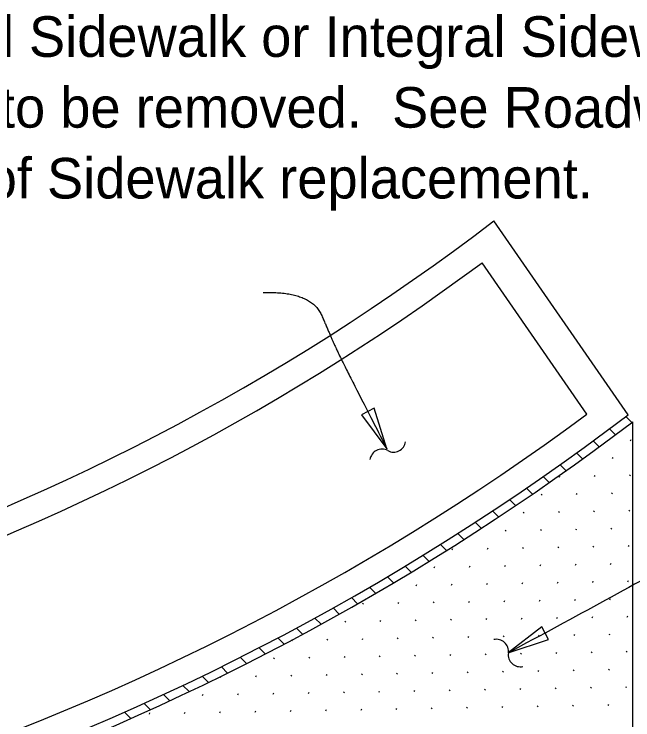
# Model space of a CAD drawing. Extents: x 21526.6 to 21595.9, y 56114.9 to 56157.2.
# Drawn here: x 21559.338 to 21562.412, y 56149.572 to 56153.08 of the extents above; entities that cross this region are included whole.
import ezdxf

# ---------------------------------------------------------------- set-up
doc = ezdxf.new("R2010")
doc.units = 0
for name, color, linetype in [('AdhocPoint_dp', 7, 'Continuous'), ('Patterning', 7, 'Continuous'), ('PlotBorder_dp', 7, 'Continuous')]:
    doc.layers.add(name, color=color, linetype=linetype)

msp = doc.modelspace()

# ---------------------------------------------------------------- linework, layer by layer
at = {"layer": 'AdhocPoint_dp'}
for p, q in [((21562.3881, 56151.0884), (21561.7207, 56152.0524)), ((21562.1837, 56151.0913), (21561.6624, 56151.8443)), ((21562.4118, 56147.2732), (21562.4118, 56151.0541))]:
    msp.add_line(p, q, dxfattribs=at)
for radius, start, end in [(11.3394, 267.40102, 307.51098), (11.4702, 267.84731, 306.6471), (12.5106, 267.64448, 307.24718), (12.3856, 268.00648, 306.50279), (12.5523, 272.40859, 307.2387)]:
    msp.add_arc((21554.816, 56161.0472), radius, start, end, dxfattribs=at)
at = {"layer": 'Patterning'}
for p, q in [((21562.3762, 56151.0794), (21562.4058, 56151.0498)), ((21562.2955, 56151.0186), (21562.3249, 56150.9892)), ((21562.2142, 56150.9585), (21562.244, 56150.9287)), ((21562.4004, 56150.9596), (21562.4036, 56150.9652)), ((21562.1323, 56150.899), (21562.1618, 56150.8695)), ((21562.3111, 56150.8703), (21562.3143, 56150.8759)), ((21562.0498, 56150.84), (21562.0796, 56150.8103)), ((21561.9668, 56150.7817), (21561.9964, 56150.7521)), ((21562.0465, 56150.7778), (21562.0497, 56150.7834)), ((21562.2218, 56150.781), (21562.2251, 56150.7866)), ((21562.3971, 56150.7843), (21562.4004, 56150.7899)), ((21561.8831, 56150.7239), (21561.9128, 56150.6942)), ((21561.9572, 56150.6885), (21561.9605, 56150.6941)), ((21562.1325, 56150.6918), (21562.1358, 56150.6974)), ((21562.3078, 56150.695), (21562.3111, 56150.7006)), ((21561.7989, 56150.6667), (21561.8286, 56150.637)), ((21561.714, 56150.6102), (21561.7438, 56150.5804)), ((21561.868, 56150.5993), (21561.8712, 56150.6048)), ((21562.0433, 56150.6025), (21562.0465, 56150.6081)), ((21562.2186, 56150.6057), (21562.2218, 56150.6113)), ((21562.3939, 56150.609), (21562.3971, 56150.6146)), ((21561.6286, 56150.5542), (21561.6586, 56150.5242)), ((21561.7787, 56150.51), (21561.7819, 56150.5156)), ((21561.954, 56150.5132), (21561.9572, 56150.5188)), ((21562.1293, 56150.5165), (21562.1325, 56150.5221)), ((21562.3046, 56150.5197), (21562.3078, 56150.5253)), ((21561.5425, 56150.4988), (21561.5723, 56150.469)), ((21561.4559, 56150.4441), (21561.4861, 56150.4138)), ((21561.5141, 56150.4175), (21561.5174, 56150.4231)), ((21561.6894, 56150.4207), (21561.6927, 56150.4263)), ((21561.8647, 56150.4239), (21561.868, 56150.4295)), ((21562.04, 56150.4272), (21562.0433, 56150.4328)), ((21562.2153, 56150.4304), (21562.2186, 56150.436)), ((21562.3906, 56150.4337), (21562.3939, 56150.4393)), ((21561.3686, 56150.3899), (21561.3985, 56150.36)), ((21561.6001, 56150.3314), (21561.6034, 56150.337)), ((21561.7755, 56150.3347), (21561.7787, 56150.3403)), ((21561.9508, 56150.3379), (21561.954, 56150.3435)), ((21562.1261, 56150.3412), (21562.1293, 56150.3468)), ((21562.3014, 56150.3444), (21562.3046, 56150.35)), ((21561.2807, 56150.3364), (21561.3109, 56150.3062)), ((21561.4248, 56150.3282), (21561.4281, 56150.3338)), ((21561.1922, 56150.2834), (21561.2223, 56150.2534)), ((21561.3356, 56150.2389), (21561.3388, 56150.2445)), ((21561.5109, 56150.2422), (21561.5141, 56150.2478)), ((21561.6862, 56150.2454), (21561.6894, 56150.251)), ((21561.8615, 56150.2486), (21561.8647, 56150.2542)), ((21562.0368, 56150.2519), (21562.04, 56150.2575)), ((21562.2121, 56150.2551), (21562.2153, 56150.2607)), ((21562.3874, 56150.2584), (21562.3906, 56150.264)), ((21561.1031, 56150.2311), (21561.1333, 56150.2009)), ((21561.0134, 56150.1795), (21561.0436, 56150.1492)), ((21561.5969, 56150.1561), (21561.6001, 56150.1617)), ((21561.7722, 56150.1594), (21561.7755, 56150.165)), ((21561.9475, 56150.1626), (21561.9508, 56150.1682)), ((21562.1228, 56150.1659), (21562.1261, 56150.1715)), ((21562.2981, 56150.1691), (21562.3014, 56150.1747)), ((21560.923, 56150.1284), (21560.9533, 56150.0981)), ((21561.071, 56150.1464), (21561.0742, 56150.152)), ((21561.2463, 56150.1496), (21561.2495, 56150.1552)), ((21561.4216, 56150.1529), (21561.4248, 56150.1585)), ((21560.832, 56150.078), (21560.8624, 56150.0475)), ((21560.9817, 56150.0571), (21560.985, 56150.0627)), ((21561.157, 56150.0604), (21561.1603, 56150.066)), ((21561.3323, 56150.0636), (21561.3356, 56150.0692)), ((21561.5076, 56150.0669), (21561.5109, 56150.0725)), ((21561.6829, 56150.0701), (21561.6862, 56150.0757)), ((21561.8582, 56150.0733), (21561.8615, 56150.0789)), ((21562.0335, 56150.0766), (21562.0368, 56150.0822)), ((21562.2088, 56150.0798), (21562.2121, 56150.0854)), ((21562.3842, 56150.0831), (21562.3874, 56150.0887)), ((21560.7403, 56150.0282), (21560.7707, 56149.9978)), ((21561.5937, 56149.9808), (21561.5969, 56149.9864)), ((21561.769, 56149.9841), (21561.7722, 56149.9897)), ((21561.9443, 56149.9873), (21561.9475, 56149.9929)), ((21562.1196, 56149.9905), (21562.1228, 56149.9961)), ((21562.2949, 56149.9938), (21562.2981, 56149.9994)), ((21560.648, 56149.9791), (21560.6787, 56149.9484)), ((21560.7171, 56149.9646), (21560.7204, 56149.9702)), ((21560.8925, 56149.9679), (21560.8957, 56149.9735)), ((21561.0678, 56149.9711), (21561.071, 56149.9767)), ((21561.2431, 56149.9743), (21561.2463, 56149.9799)), ((21561.4184, 56149.9776), (21561.4216, 56149.9832)), ((21560.5551, 56149.9306), (21560.5856, 56149.9001)), ((21560.4615, 56149.8828), (21560.4925, 56149.8518)), ((21560.6279, 56149.8753), (21560.6311, 56149.8809)), ((21560.8032, 56149.8786), (21560.8064, 56149.8842)), ((21560.9785, 56149.8818), (21560.9817, 56149.8874)), ((21561.1538, 56149.8851), (21561.157, 56149.8907)), ((21561.3291, 56149.8883), (21561.3323, 56149.8939)), ((21561.5044, 56149.8916), (21561.5076, 56149.8972)), ((21561.6797, 56149.8948), (21561.6829, 56149.9004)), ((21561.855, 56149.898), (21561.8582, 56149.9036)), ((21562.0303, 56149.9013), (21562.0335, 56149.9069)), ((21562.2056, 56149.9045), (21562.2088, 56149.9101)), ((21562.3809, 56149.9078), (21562.3842, 56149.9134)), ((21560.3672, 56149.8357), (21560.3979, 56149.8049)), ((21561.5904, 56149.8055), (21561.5937, 56149.8111)), ((21561.7657, 56149.8088), (21561.769, 56149.8144)), ((21561.941, 56149.812), (21561.9443, 56149.8176)), ((21562.1163, 56149.8152), (21562.1196, 56149.8208)), ((21562.2916, 56149.8185), (21562.2949, 56149.8241)), ((21560.2723, 56149.7892), (21560.3034, 56149.7581)), ((21560.3633, 56149.7828), (21560.3665, 56149.7884)), ((21560.5386, 56149.7861), (21560.5418, 56149.7917)), ((21560.7139, 56149.7893), (21560.7171, 56149.7949)), ((21560.8892, 56149.7926), (21560.8925, 56149.7982)), ((21561.0645, 56149.7958), (21561.0678, 56149.8014)), ((21561.2398, 56149.799), (21561.2431, 56149.8046)), ((21561.4151, 56149.8023), (21561.4184, 56149.8079)), ((21560.1767, 56149.7433), (21560.2076, 56149.7124)), ((21560.6246, 56149.7), (21560.6279, 56149.7056)), ((21560.7999, 56149.7033), (21560.8032, 56149.7089)), ((21560.9752, 56149.7065), (21560.9785, 56149.7121)), ((21561.1505, 56149.7098), (21561.1538, 56149.7154)), ((21561.3258, 56149.713), (21561.3291, 56149.7186)), ((21561.5012, 56149.7163), (21561.5044, 56149.7218)), ((21561.6765, 56149.7195), (21561.6797, 56149.7251)), ((21561.8518, 56149.7227), (21561.855, 56149.7283)), ((21562.0271, 56149.726), (21562.0303, 56149.7316)), ((21562.2024, 56149.7292), (21562.2056, 56149.7348)), ((21562.3777, 56149.7325), (21562.3809, 56149.7381)), ((21560.0804, 56149.6982), (21560.1116, 56149.667)), ((21560.274, 56149.6936), (21560.2773, 56149.6992)), ((21560.4493, 56149.6968), (21560.4526, 56149.7024)), ((21559.9835, 56149.6537), (21560.0146, 56149.6226)), ((21561.5872, 56149.6302), (21561.5904, 56149.6358)), ((21561.7625, 56149.6335), (21561.7657, 56149.6391)), ((21561.9378, 56149.6367), (21561.941, 56149.6423)), ((21562.1131, 56149.6399), (21562.1163, 56149.6455)), ((21562.2884, 56149.6432), (21562.2916, 56149.6488)), ((21559.8858, 56149.6099), (21559.9171, 56149.5786)), ((21560.0095, 56149.6011), (21560.0127, 56149.6066)), ((21560.1848, 56149.6043), (21560.188, 56149.6099)), ((21560.3601, 56149.6075), (21560.3633, 56149.6131)), ((21560.5354, 56149.6108), (21560.5386, 56149.6164)), ((21560.7107, 56149.614), (21560.7139, 56149.6196)), ((21560.886, 56149.6173), (21560.8892, 56149.6229)), ((21561.0613, 56149.6205), (21561.0645, 56149.6261)), ((21561.2366, 56149.6237), (21561.2398, 56149.6293)), ((21561.4119, 56149.627), (21561.4151, 56149.6326))]:
    msp.add_line(p, q, dxfattribs=at)
at = {"layer": 'PlotBorder_dp'}
for points in [[(21561.1899, 56150.9199), (21561.1259, 56151.1212), (21561.0632, 56151.0888)], [(21561.7926, 56149.9047), (21561.993, 56149.9714), (21561.9599, 56150.0337)]]:
    msp.add_lwpolyline(points, close=True, dxfattribs=at)
for centre, start, end in [((21561.2231, 56150.9622), 240.6805, 352.4077), ((21561.1648, 56150.8582), 60.6805, 172.4077), ((21561.7341, 56149.9128), 351.6288, 103.356), ((21561.8521, 56149.8955), 171.6288, 283.356)]:
    msp.add_arc(centre, 0.0596, start, end, dxfattribs=at)
for points in [[(21563.882, 56152.2347), (21564.3729, 56152.2347), (21564.5784, 56151.9606), (21564.1103, 56151.1382), (21561.7926, 56149.9047)], [(21560.5748, 56151.6957), (21560.8133, 56151.7039), (21560.9181, 56151.4604), (21560.9728, 56151.3412), (21561.1899, 56150.9199)], [(21563.3959, 56149.8682), (21562.6714, 56149.9081), (21562.2001, 56149.0388), (21561.8851, 56147.8698), (21561.6576, 56146.9593)]]:
    msp.add_open_spline(points, degree=2, dxfattribs=at)

# ---------------------------------------------------------------- texts
for s, p in [('Existing Detached Sidewalk or Integral Sidewalk ', (21557.1636, 56152.8674)), ('less than 6" thick to be removed.  See Roadway ', (21557.1636, 56152.5154)), ('Plans for Details of Sidewalk replacement.', (21557.1636, 56152.1634))]:
    msp.add_text(s, height=0.2016, dxfattribs=at).set_placement(p)

doc.saveas('drawing.dxf')
